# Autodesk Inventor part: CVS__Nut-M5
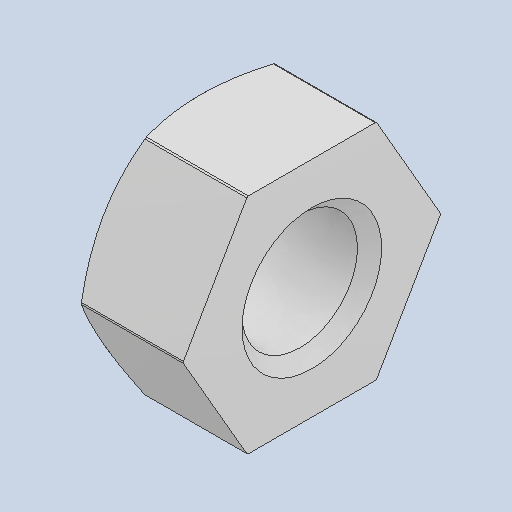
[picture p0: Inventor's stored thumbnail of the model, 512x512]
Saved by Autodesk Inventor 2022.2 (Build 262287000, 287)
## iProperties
Created: 2024-10
Part Number: CVS__Nut-M5
Material: Generico
Document SubType Name: Modeling
Designer: 18907419
Density: 1 g/cm^3
Appearance: Default
Author: 18907419
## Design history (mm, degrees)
feature "Solido1"
node "Solido2"
